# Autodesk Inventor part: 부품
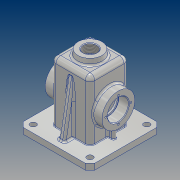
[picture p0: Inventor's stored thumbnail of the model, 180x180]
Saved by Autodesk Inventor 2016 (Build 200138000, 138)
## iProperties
Created: 2018-10
Part Number: 부품
Material: 알루미늄 6061
Document SubType Name: Modeling
Designer: user
Density: 2.7 g/cm^3
Appearance: 알루미늄 - 평지
Mass: 792.964 g
Surface Area: 901.916 cm^2
Volume: 293.69 cm^3
Author: user
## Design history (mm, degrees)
sketch "스케치1"
  geometry: 1 further point
sketch "스케치2"
  geometry: L1 (60, -60)-(-60, -60); L2 (-60, -60)-(-60, 60); L3 (-60, 60)-(60, 60); L4 (60, 60)-(60, -60); L5 (60, -60)-(-60, 60); L6 (-60, -60)-(60, 60); 1 further point
  constraints: 12 end point, 2 midpoint, 2 parallel, 1 horizontal, 1 perpendicular
  dimensions: "d0" = 120 distance of L2.end L3.end; "d1" = 120 distance of L1.end L2.end
extrude "돌출1" new body sketch "스케치2" distance "d2" = 10; taper "d3" = 0 deg
sketch "스케치3"
  geometry: L1 (-32.5, 32.5)-(32.5, 32.5); L2 (32.5, 32.5)-(32.5, -32.5); L3 (32.5, -32.5)-(-32.5, -32.5); L4 (-32.5, -32.5)-(-32.5, 32.5); L5 (-32.5, 32.5)-(32.5, -32.5); L6 (32.5, 32.5)-(-32.5, -32.5); 1 further point
  constraints: 12 end point, 2 midpoint, 2 parallel, 1 horizontal, 1 perpendicular
  dimensions: "d4" = 65 distance of L2.end L3.end; "d5" = 65 distance of L1.end L2.end
extrude "돌출2" join sketch "스케치3" distance "d6" = 100; taper "d7" = 0 deg
sketch "스케치4"
  geometry: L1 (-27.5, 27.5)-(27.5, 27.5); L2 (27.5, 27.5)-(27.5, -27.5); L3 (27.5, -27.5)-(-27.5, -27.5); L4 (-27.5, -27.5)-(-27.5, 27.5); L5 (-27.5, 27.5)-(27.5, -27.5); L6 (27.5, 27.5)-(-27.5, -27.5); 1 further point
  constraints: 12 end point, 2 midpoint, 2 parallel, 1 horizontal, 1 perpendicular
  dimensions: "d8" = 55 distance of L2.end L3.end; "d9" = 55 distance of L1.end L2.end
extrude "돌출3" cut sketch "스케치4" distance "d10" = 105; taper "d11" = 0 deg
chamfer "모따기1" distance "d12" = 8; stored, may be unused: second distance "d13" = 2, angle "d14" = 45 deg
fillet "모깎기1" dims "d15" = 8
fillet "모깎기2" dims "d16" = 8
sketch "스케치5"
  geometry: L1 (76.5, -10)-(-27.5, -10) reference; C1 r 27.5 at (24.5, 45); 2 further points
  constraints: 1 centre point, 1 midpoint, 1 vertical alignment
  dimensions: "d17" = 55 diameter of C1; "d18" = 55 distance from line of L1 C1.centre
extrude "돌출4" join sketch "스케치5" distance "d19" = 15; taper "d20" = 0 deg
node "작업 평면1"
sketch "스케치6"
  geometry: C1 r 27.5 at (0, 0) reference; C2 r 17.5 at (0, 0); 1 further point
  constraints: 1 centre point, 1 coincident
  dimensions: "d22" = 35 diameter of C2
extrude "돌출5" cut sketch "스케치6" stored distance "d23" = 15; taper "d24" = 0 deg
hole "구멍1" diameter "d27" = 30; stored, may be unused: countersink angle "d31" = 90 deg, drill point angle "d33" = 118 deg; dims "d25" = 10, "d26" = 10, "d28" = 6, "d29" = 4, "d30" = 2, "d32" = 8
node "작업 평면2"
sketch "스케치7"
  geometry: C1 r 20 at (0, 0); 1 further point
  constraints: 1 centre point, 1 coincident
  dimensions: "d35" = 40 diameter of C1
extrude "돌출6" join sketch "스케치7" distance "d36" = 15; taper "d37" = 7 deg
hole "구멍2" diameter "d40" = 22.835; stored, may be unused: countersink angle "d44" = 90 deg, drill point angle "d46" = 118 deg; dims "d38" = 10, "d39" = 10, "d41" = 50, "d42" = 4, "d43" = 2, "d45" = 59.3
fillet "모깎기3" dims "d47" = 0.3
fillet "모깎기4" dims "d48" = 3
fillet "모깎기5" dims "d49" = 3
sketch "스케치8"
  geometry: L1 (10, -52)-(10, -60) reference; L2 (102, -32.5)-(10, -32.5) reference; L3 (0, 60)-(10, 60) reference; L4 (10, 60)-(10, 32.5) reference; L5 (10, 32.5)-(102, 32.5) reference; L6 (110, 24.5)-(110, 21.228) reference; L7 (110, 21.228)-(120, 20) reference; L8 (120, 20)-(120, 11.418) reference; L9 (120, 11.418)-(105, 11.418) reference; L10 (105, 11.418)-(105, 24.5) reference; L11 (102, 27.5)-(0, 27.5) reference; L12 (0, 27.5)-(0, 60) reference; L13 (0, -60)-(0, -27.5) reference; L14 (0, -27.5)-(102, -27.5) reference; L15 (105, -24.5)-(105, -11.418) reference; L16 (105, -11.418)-(120, -11.418) reference; L17 (120, -11.418)-(120, -20) reference; L18 (120, -20)-(110, -21.228) reference; L19 (110, -21.228)-(110, -24.5) reference; L20 (102, -32.5)-(10, -32.5) reference; L21 (10, -32.5)-(10, -60) reference; L22 (10, -60)-(0, -60) reference; L23 (10, -48)-(97.905, -32.5); A1 r 8 centre (102, 24.5) between (110, 24.5) and (102, 32.5) reference; A2 r 3 centre (102, 24.5) between (105, 24.5) and (102, 27.5) reference; A3 r 3 centre (102, -24.5) between (102, -27.5) and (105, -24.5) reference; A4 r 8 centre (102, -24.5) between (102, -32.5) and (110, -24.5) reference; 1 further point
  constraints: 2 end point, 2 point on line
  dimensions: "d50" = 12 distance from line of L22 L23.start; "d51" = 10 deg angle of L22 L23
  node "절단 모서리 투영1"
sketch "스케치9"
  geometry: L1 (47.5, 27.5)-(32.5, 27.5) reference; L2 (32.5, 27.5)-(32.5, 10) reference; L3 (32.5, 10)-(60, 10) reference; L4 (60, 10)-(60, 0) reference; L5 (60, 0)-(27.5, 0) reference; L6 (27.5, 0)-(27.5, 40) reference; L7 (27.5, 40)-(30.5, 40) reference; L8 (30.5, 40)-(30.5, 37.8) reference; L9 (30.8, 37.5)-(47.5, 37.5) reference; L10 (47.5, 37.5)-(47.5, 27.5) reference; L11 (32.5, 82.5)-(47.5, 82.5) reference; L12 (47.5, 82.5)-(47.5, 72.5) reference; L13 (47.5, 72.5)-(30.8, 72.5) reference; L14 (30.5, 72.2)-(30.5, 70) reference; L15 (30.5, 70)-(27.5, 70) reference; L16 (27.5, 70)-(27.5, 102) reference; L17 (24.5, 105)-(11.418, 105) reference; L18 (11.418, 105)-(11.418, 120) reference; L19 (11.418, 120)-(20, 120) reference; L20 (20, 120)-(21.228, 110) reference; L21 (21.228, 110)-(24.5, 110) reference; L22 (32.5, 102)-(32.5, 82.5) reference; L23 (-32.5, 27.5)-(-47.5, 27.5) reference; L24 (-47.5, 27.5)-(-47.5, 37.5) reference; L25 (-47.5, 37.5)-(-30.8, 37.5) reference; L26 (-30.5, 37.8)-(-30.5, 40) reference; L27 (-30.5, 40)-(-27.5, 40) reference; L28 (-27.5, 40)-(-27.5, 0) reference; L29 (-27.5, 0)-(-60, 0) reference; L30 (-60, 0)-(-60, 10) reference; L31 (-60, 10)-(-32.5, 10) reference; L32 (-32.5, 10)-(-32.5, 27.5) reference; L33 (-47.5, 82.5)-(-32.5, 82.5) reference; L34 (-32.5, 82.5)-(-32.5, 102) reference; L35 (-24.5, 110)-(-21.228, 110) reference; L36 (-21.228, 110)-(-20, 120) reference; L37 (-20, 120)-(-11.418, 120) reference; L38 (-11.418, 120)-(-11.418, 105) reference; L39 (-11.418, 105)-(-24.5, 105) reference; L40 (-27.5, 102)-(-27.5, 70) reference; L41 (-27.5, 70)-(-30.5, 70) reference; L42 (-30.5, 70)-(-30.5, 72.2) reference; L43 (-30.8, 72.5)-(-47.5, 72.5) reference; L44 (-47.5, 72.5)-(-47.5, 82.5) reference; L45 (42.5, 27.5)-(42.5, 10); L46 (-52, 10)-(52, 10) reference; L47 (47.5, 27.5)-(32.5, 27.5) reference; L48 (32.5, 27.5)-(32.5, 10) reference; L49 (32.5, 10)-(60, 10) reference; L50 (60, 10)-(60, 0) reference; L51 (60, 0)-(27.5, 0) reference; L52 (27.5, 0)-(27.5, 40) reference; L53 (27.5, 40)-(30.5, 40) reference; L54 (30.5, 40)-(30.5, 37.8) reference; L55 (30.8, 37.5)-(47.5, 37.5) reference; L56 (47.5, 37.5)-(47.5, 27.5) reference; L57 (32.5, 82.5)-(47.5, 82.5) reference; L58 (47.5, 82.5)-(47.5, 72.5) reference; L59 (47.5, 72.5)-(30.8, 72.5) reference; L60 (30.5, 72.2)-(30.5, 70) reference; L61 (30.5, 70)-(27.5, 70) reference; L62 (27.5, 70)-(27.5, 102) reference; L63 (24.5, 105)-(11.418, 105) reference; L64 (11.418, 105)-(11.418, 120) reference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; A1 r 0.3 centre (30.8, 37.8) between (30.5, 37.8) and (30.8, 37.5) reference; A2 r 0.3 centre (30.8, 72.2) between (30.8, 72.5) and (30.5, 72.2) reference; A3 r 3 centre (24.5, 102) between (27.5, 102) and (24.5, 105) reference; A4 r 8 centre (24.5, 102) between (32.5, 102) and (24.5, 110) reference; A5 r 0.3 centre (-30.8, 37.8) between (-30.8, 37.5) and (-30.5, 37.8) reference; A6 r 8 centre (-24.5, 102) between (-24.5, 110) and (-32.5, 102) reference; A7 r 3 centre (-24.5, 102) between (-24.5, 105) and (-27.5, 102) reference; A8 r 0.3 centre (-30.8, 72.2) between (-30.5, 72.2) and (-30.8, 72.5) reference; A9 r 0.3 centre (30.8, 37.8) between (30.5, 37.8) and (30.8, 37.5) reference; A10 r 0.3 centre (30.8, 72.2) between (30.8, 72.5) and (30.5, 72.2) reference; A11 r 3 centre (24.5, 102) between (27.5, 102) and (24.5, 105) reference; A12 r 8 centre (24.5, 102) between (32.5, 102) and (24.5, 110) reference; A13 r 0.3 centre (-30.8, 37.8) between (-30.8, 37.5) and (-30.5, 37.8) reference; A14 r 8 centre (-24.5, 102) between (-24.5, 110) and (-32.5, 102) reference; A15 r 3 centre (-24.5, 102) between (-24.5, 105) and (-27.5, 102) reference; A16 r 0.3 centre (-30.8, 72.2) between (-30.5, 72.2) and (-30.8, 72.5) reference; 1 further point
  constraints: 2 end point, 2 point on line, 1 perpendicular
  dimensions: "d54" = 15 distance between parallel lines of L6 L45
feature "리브1" sketch "스케치9" dims "d55" = 1, "d56" = 6, "d57" = 0, "d58" = 0, "d59" = 1, "d60" = 1
feature "리브2" dims "d61" = 1, "d62" = 10, "d63" = 0, "d64" = 0, "d65" = 1, "d66" = 1
sketch "스케치10"
  geometry: C1 r 17.5 at (0, 0) reference; 2 further points
  constraints: 1 vertical alignment
  dimensions: "d67" = 21 distance of C1.centre point (0, 21)
hole "구멍3" sketch "스케치10" at (0, 21) diameter "d68" = 3.242; stored, may be unused: countersink angle "d72" = 90 deg, drill point angle "d74" = 118 deg; dims "d69" = 8, "d70" = 4, "d71" = 2, "d73" = 10
sketch "스케치11"
  geometry: L1 (-47.5, 47.5)-(47.5, 47.5); L2 (47.5, 47.5)-(47.5, -47.5); L3 (47.5, -47.5)-(-47.5, -47.5); L4 (-47.5, -47.5)-(-47.5, 47.5); L5 (-47.5, 47.5)-(47.5, -47.5); L6 (47.5, 47.5)-(-47.5, -47.5); C1 r 5 at (-47.5, 47.5); C2 r 5 at (-47.5, -47.5); C3 r 5 at (47.5, -47.5); C4 r 5 at (47.5, 47.5); 1 further point
  constraints: 12 end point, 4 centre point, 4 coincident, 2 midpoint, 2 parallel, 1 horizontal, 1 perpendicular
  dimensions: "d78" = 95 distance of L2.end L3.end; "d79" = 95 distance of L1.end L2.end; "d80" = 10 diameter of C1; "d81" = 10 diameter of C2; "d82" = 10 diameter of C3; "d83" = 10 diameter of C4
extrude "돌출8" cut sketch "스케치11" stored distance "d84" = 10; taper "d85" = 0 deg
fillet "모깎기6" dims "d86" = 3
fillet "모깎기7" dims "d87" = 3
fillet "모깎기8" dims "d88" = 3
fillet "모깎기9" dims "d89" = 3
fillet "모깎기10" dims "d90" = 3
chamfer "모따기2" distance "d91" = 1; stored, may be unused: second distance "d92" = 2, angle "d93" = 45 deg
chamfer "모따기3" distance "d94" = 1; stored, may be unused: second distance "d95" = 2, angle "d96" = 45 deg
chamfer "모따기4" distance "d97" = 1; stored, may be unused: second distance "d98" = 2, angle "d99" = 45 deg
fillet "모깎기11" dims "d100" = 3
sketch "스케치12"
  geometry: L1 (4.5, 18)-(44.5, 18) reference; A1 r 30.5 centre (24.5, -47) between (49, -28.834) and (0, -28.834) reference; 2 further points
  constraints: 1 vertical alignment, 1 other
  dimensions: "d101" = 26 distance from line of point (24.5, -8) L1
feature "엠보싱1" sketch "스케치12" dims "d102" = 0.5, "d103" = 0
fillet "모깎기12" dims "d104" = 1
fillet "모깎기13" dims "d105" = 1
fillet "모깎기15" dims "d107" = 3
node "솔리드1"
mirror "대칭1"
mirror "대칭3"
mirror "대칭4"
pattern_circular "원형 패턴1" dims angle "d76" = 360 deg
mirror "대칭5"
node "투영된 루프1"
node "절단 모서리 투영2"
node "절단 모서리 투영3"
other parameters: "d21" = -17
